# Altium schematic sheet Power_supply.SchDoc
size A3; SheetNumber: 1; SheetTotal: 1
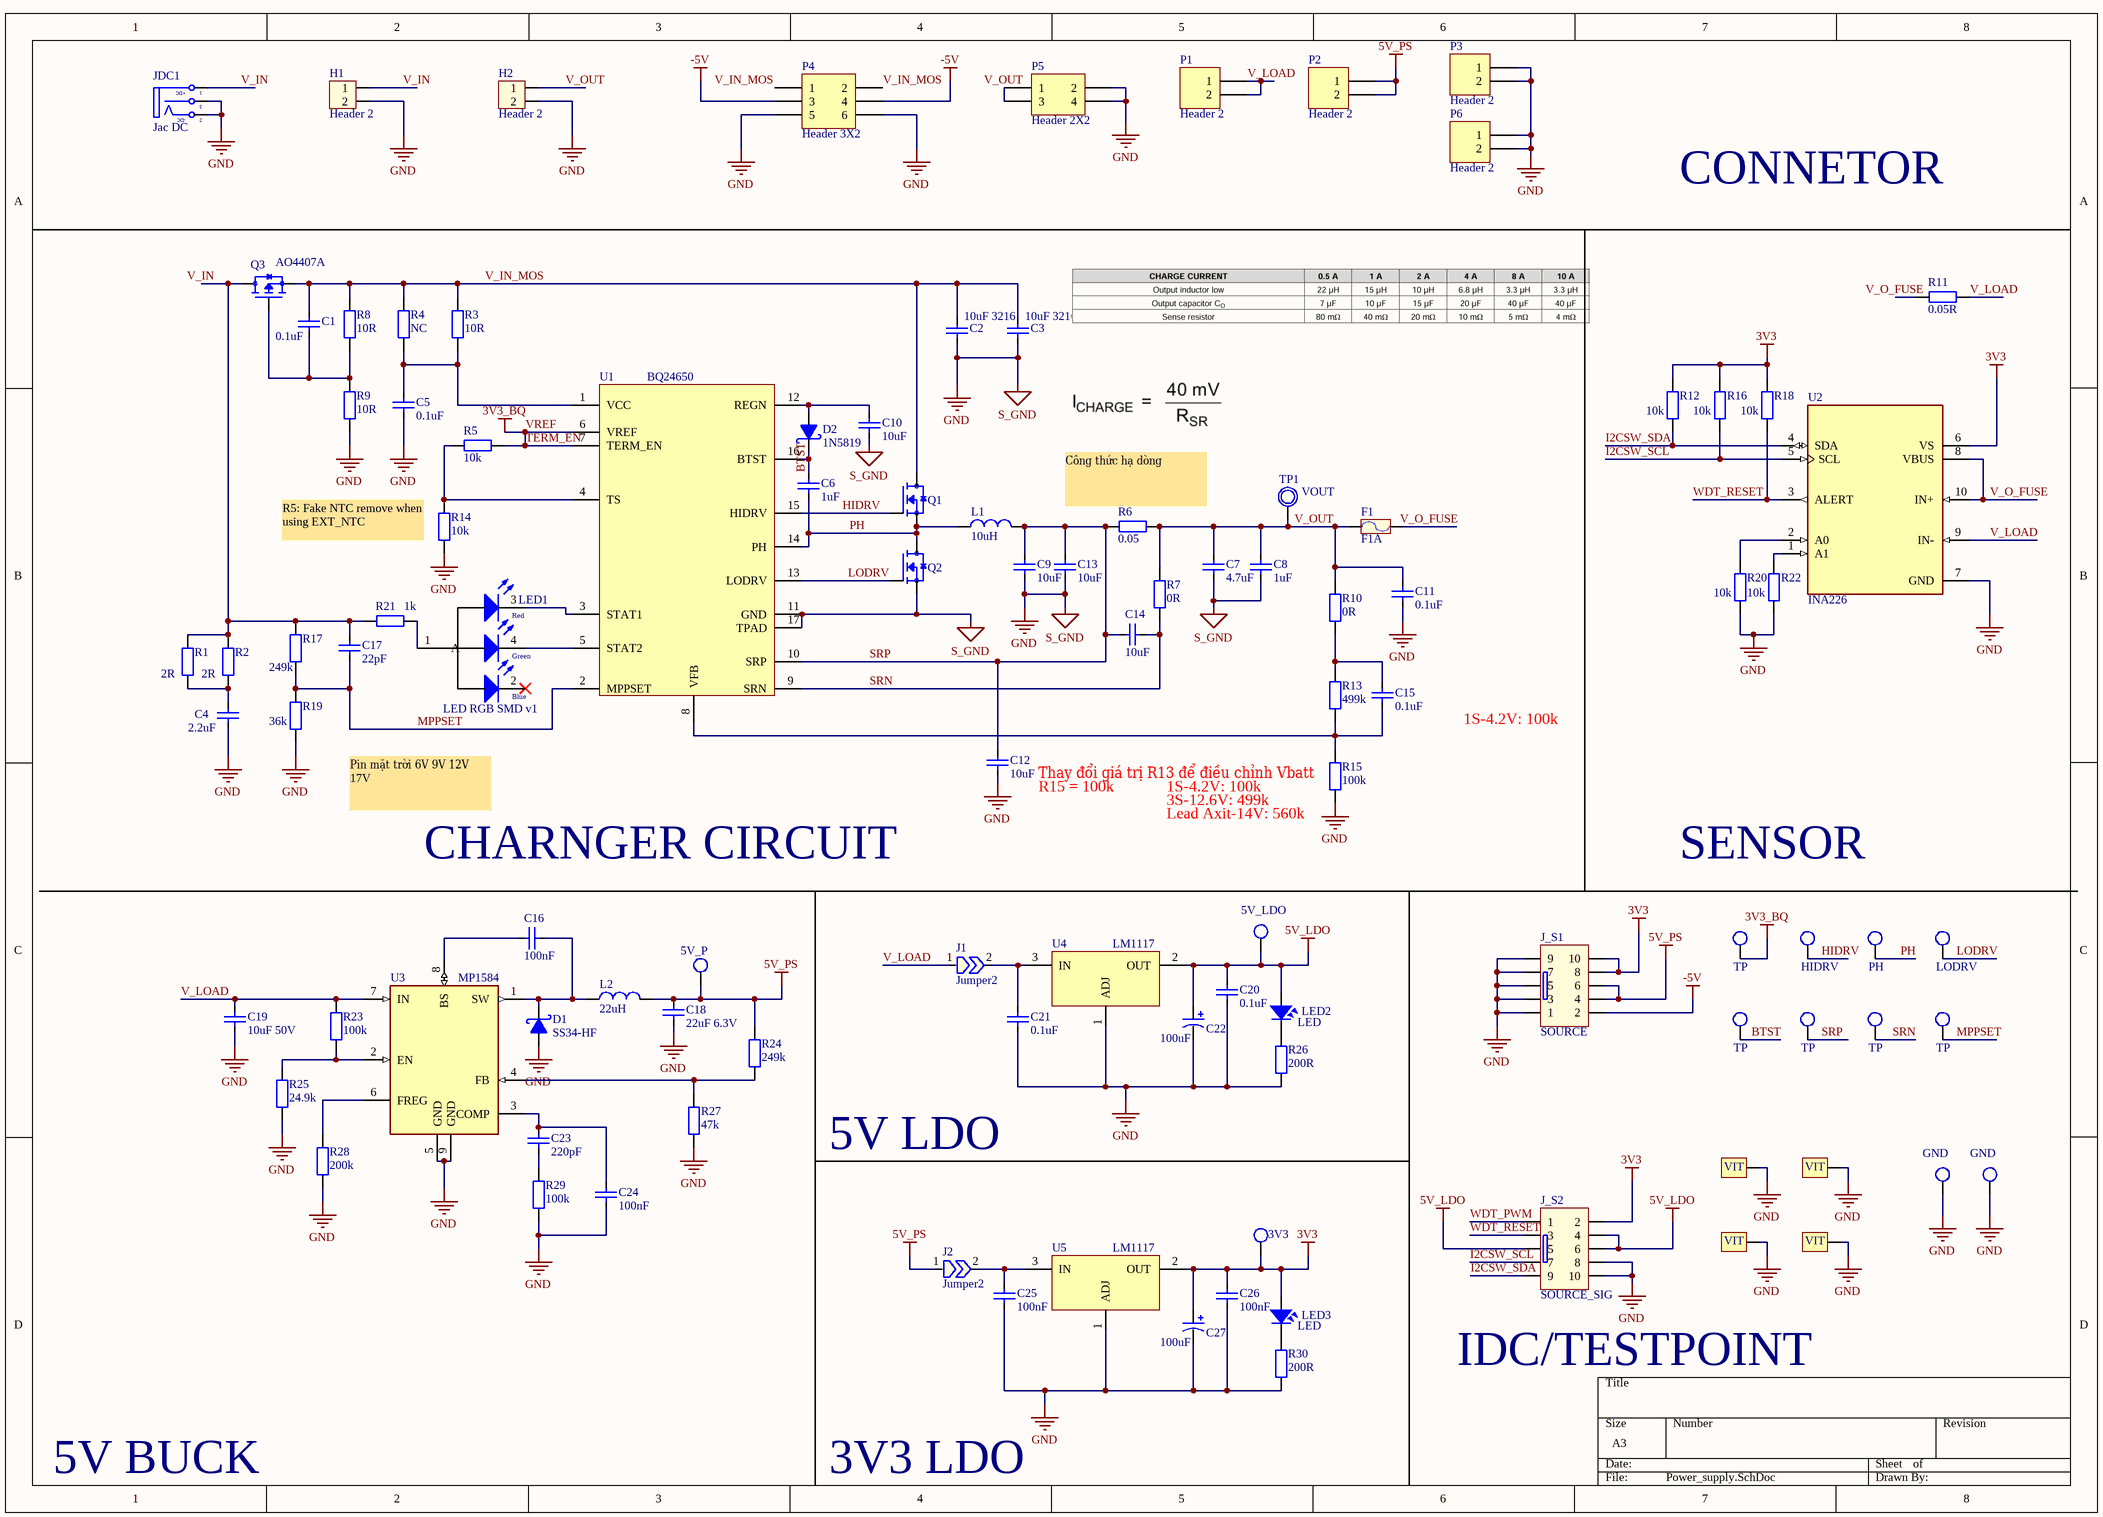
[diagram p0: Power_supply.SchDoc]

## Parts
C1  0.1uF  [CAP_0805]
C2  10uF 3216  [CAP_3216]
C3  10uF 3216  [CAP_3216]
C4  2.2uF  [CAP_0805]
C5  0.1uF  [CAP_0805]
C6  1uF  [CAP_0805]
C7  4.7uF  [CAP_1206]
C8  1uF  [CAP_1206]
C9  10uF  [CAP_1206]
C10  10uF  [CAP_0805]
C11  0.1uF  [CAP_0805]
C12  10uF  [CAP_0805]
C13  10uF  [CAP_1206]
C14  10uF  [CAP_0805]
C15  0.1uF  [CAP_0805]
C16  100nF  [CAP_0805]
C17  22pF  [CAP_0805]
C18  22uF 6.3V  [CAP_0805]
C19  10uF 50V  [CAP_3216]
C20  0.1uF  [CAP_0805]
C21  0.1uF  [CAP_0805]
C22  100uF  [CAP_7343]
C23  220pF  [CAP_0805]
C24  100nF  [CAP_0805]
C25  100nF  [CAP_0805]
C26  100nF  [CAP_0805]
C27  100uF  [CAP_7343]
D1  SS34-HF  [SMA]
D2  1N5819  [SMA]
F1  F1A  [RES-SMD-1812]
H1  Header 2  [HED2]
H2  Header 2  [HED2]
J1  Jumper2  [JUMPER2]  (no BOM)
J2  Jumper2  [JUMPER2]  (no BOM)
J_S1  SOURCE  [IDC10]
J_S2  SOURCE_SIG  [IDC10]
JDC1  Jac DC  [DC-IN]
L1  10uH  [L-SMD-M-12x10]
L2  22uH  [L-SMD-M-7.3x4.5]
LED1  LED RGB SMD v1  [LED RGB 3528]
LED2  LED  [LED-0805-Blue]
LED3  LED  [LED-0805-Blue]
P1  Header 2  [HDR1X2]
P2  Header 2  [HDR1X2]
P3  Header 2  [HDR1X2]
P4  Header 3X2  [HDR2X3]
P5  Header 2X2  [HDR2X2]
P6  Header 2  [HDR1X2]
P7  5V_P  [Testpoint 50ml]  (no BOM)
P8  5V_LDO  [Testpoint 50ml]  (no BOM)
P9  GND  [Testpoint 50ml]  (no BOM)
P10  GND  [Testpoint 50ml]  (no BOM)
P11  3V3  [Testpoint 50ml]  (no BOM)
Q1  AON6508  [MOSFET_HP_8Pin]  (value not drawn)
Q2  AON6508  [MOSFET_HP_8Pin]  (value not drawn)
Q3  AO4407A  [SOIC-8]
R1  2R  [RES-SMD-2512]
R2  2R  [RES-SMD-2512]
R3  10R  [RES-SMD-0805]
R4  NC  [RES-SMD-0805]
R5  10k  [RES-SMD-0805]
R6  0.05  [RES-SMD-2512]
R7  0R  [RES-SMD-0805]
R8  10R  [RES-SMD-0805]
R9  10R  [RES-SMD-0805]
R10  0R  [RES-SMD-0805]
R11  0.05R  [RES-SMD-2512]
R12  10k  [RES-SMD-0805]
R13  499k  [RES-SMD-0805]
R14  10k  [RES-SMD-0805]
R15  100k  [RES-SMD-0805]
R16  10k  [RES-SMD-0805]
R17  249k  [RES-SMD-0805]
R18  10k  [RES-SMD-0805]
R19  36k  [RES-SMD-0805]
R20  10k  [RES-SMD-0805]
R21  1k  [RES-SMD-0805]
R22  10k  [RES-SMD-0805]
R23  100k  [RES-SMD-0805]
R24  249k  [RES-SMD-0805]
R25  24.9k  [RES-SMD-0805]
R26  200R  [RES-SMD-0805]
R27  47k  [RES-SMD-0805]
R28  200k  [RES-SMD-0805]
R29  100k  [RES-SMD-0805]
R30  200R  [RES-SMD-0805]
TP1  VOUT  [TP1]
TP2  TP  [Testpoint 50ml]
TP3  HIDRV  [Testpoint 50ml]
TP4  PH  [Testpoint 50ml]
TP5  LODRV  [Testpoint 50ml]
TP6  TP  [Testpoint 50ml]
TP7  TP  [Testpoint 50ml]
TP8  TP  [Testpoint 50ml]
TP9  TP  [Testpoint 50ml]
U1  BQ24650  [VQFN-16]
U2  INA226  [VSSOP-10]
U3  MP1584  [SOP8-PP]
U4  LM1117  [SOT-223]
U5  LM1117  [SOT-223]
VIT1  1  [Screw Hole 4mm]  (value not drawn)  (net tie, no BOM)
VIT2  1  [Screw Hole 4mm]  (value not drawn)  (net tie, no BOM)
VIT3  1  [Screw Hole 4mm]  (value not drawn)  (net tie, no BOM)
VIT4  1  [Screw Hole 4mm]  (value not drawn)  (net tie, no BOM)

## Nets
3V3: C26.2 C27.1 J_S1.8 J_S1.10 J_S2.2 LED3.1 P11.1 R12.1 R16.1 R18.1 U2.6(VS) U5.2(OUT)
5V_LDO: C20.2 C22.1 J_S2.4 J_S2.5 J_S2.6 LED2.1 P8.1 U4.2(OUT)
5V_PS: C18.2 J2.1 J_S1.4 J_S1.6 L2.2 P2.1 P2.2 P7.1 R24.1
-5V: J_S1.2 P4.3 P4.4
GND: C2.1 C3.1 C4.1 C5.1 C7.2 C8.2 C9.1 C10.1 C11.1 C12.1 C13.1 C18.1 C19.1 C20.1 C21.1 C22.2 C24.1 C25.1 C26.1 C27.2 D1.1(A) H1.2 H2.2 J_S1.1 J_S1.3 J_S1.5 J_S1.7 J_S1.9 J_S2.8 J_S2.10 JDC1.2(TN) JDC1.3(S) P3.1 P3.2 P4.5 P4.6 P5.2 P5.4 P6.1 P6.2 P9.1 P10.1 Q2.1,2,3(S) R9.2 R14.2 R15.2 R19.2 R20.2 R22.2 R25.2 R26.2 R27.2 R28.2 R29.2 R30.2 U1.11(GND) U1.17(TPAD) U2.7(GND) U3.5(GND) U3.9(GND) U4.1(ADJ) U5.1(ADJ) VIT1.VIT1 VIT2.VIT1 VIT3.VIT1 VIT4.VIT1  [also labelled S_GND]
TERM_EN: R5.2 TP2.1 U1.6(VREF) U1.7(TERM_EN)  [also labelled 3V3_BQ, VREF]
BTST: C6.2 D2.2(K) TP6.1 U1.16(BTST)
HIDRV: Q1.4(G) TP3.1 U1.15(HIDRV)
I2CSW_SCL: J_S2.7 R16.2 U2.5(SCL)
I2CSW_SDA: J_S2.9 R12.2 U2.4(SDA)
LODRV: Q2.4(G) TP5.1 U1.13(LODRV)
MPPSET: C17.1 R17.2 R19.1 TP9.1 U1.2(MPPSET)
PH: C6.1 L1.1 Q1.1,2,3(S) Q2.5,6,7,8,9(D) TP4.1 U1.14(PH)
SRN: C14.1 R7.2 TP8.1 U1.9(SRN)
SRP: C9.2 C12.2 C13.2 C14.2 L1.2 R6.2 TP7.1 U1.10(SRP)
V_IN: C17.2 H1.1 JDC1.1(T) Q3.5,_6,_7,_8(D) R1.1 R2.1 R17.1 R21.2
V_IN_MOS: C1.2 C2.2 C3.2 P4.1 P4.2 Q1.5,6,7,8,9(D) Q3.1,_2,_3(S) R3.1 R4.1 R8.1
V_LOAD: C19.2 J1.1 P1.1 P1.2 R11.1 R23.1 U2.9(IN-) U3.7(IN)
V_O_FUSE: F1.2 R11.2 U2.8(VBUS) U2.10(IN+)
V_OUT: C7.1 C8.1 C11.2 F1.1 H2.1 P5.1 P5.3 R6.1 R7.1 R10.1 TP1.1
WDT_PWM: J_S2.1
WDT_RESET: J_S2.3 R18.2 U2.3(ALERT)
NetC1_1: C1.1 Q3.4(G) R8.2 R9.1
NetC4_2: C4.2 R1.2 R2.2
NetC5_2: C5.2 R3.2 R4.2 U1.1(VCC)
NetC10_2: C10.2 D2.1(A) U1.12(REGN)
NetC15_1: C15.1 R13.2 R15.1 U1.8(VFB)
NetC15_2: C15.2 R10.2 R13.1
NetC16_1: C16.1 U3.8(BS)
NetC16_2: C16.2 D1.2(K) L2.1 U3.1(SW)
NetC21_2: C21.2 J1.2 U4.3(IN)
NetC23_1: C23.1 R29.1
NetC23_2: C23.2 C24.2 U3.3(COMP)
NetC25_2: C25.2 J2.2 U5.3(IN)
NetLED1_1: LED1.1(A) R21.1
NetLED1_3: LED1.3(C2) U1.3(STAT1)
NetLED1_4: LED1.4(C1) U1.5(STAT2)
NetLED2_2: LED2.2 R26.1
NetLED3_2: LED3.2 R30.1
NetR5_1: R5.1 R14.1 U1.4(TS)
NetR20_1: R20.1 U2.2(A0)
NetR22_1: R22.1 U2.1(A1)
NetR23_2: R23.2 R25.1 U3.2(EN)
NetR24_2: R24.2 R27.1 U3.4(FB)
NetR28_1: R28.1 U3.6(FREG)

Not connected (* = marked no-connect by the designer): LED1 2(C3)*

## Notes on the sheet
- CONNETOR
- (near R6) Công thức hạ dòng
- (near R14) R5: Fake NTC remove when using EXT_NTC
- 1S-4.2V: 100k
- (near R15) Thay đổi giá trị R13 để điều chỉnh Vbatt
- (near C12) R15 = 100k
- Pin mặt trời 6V 9V 12V 17V
- CHARNGER CIRCUIT
- 3S-12.6V: 499k
- (near R15) Lead Axit-14V: 560k
- SENSOR
- 5V LDO
- (near J_S2) IDC/TESTPOINT
- 5V BUCK
- 3V3 LDO

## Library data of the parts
C1-C15 C17 = CapSMD: Capacitor; Value: 33p
C16 C18 C20 C21 C23-C26 = CapSMD: C 0805; Value: 33p
C19 = CapSMD: C 1206; Value: 33p
C22 C27 = CAP_TAN_SMD: C Tan 7343
D1 D2 = 1N5822: Schottky Rectifiers; Value: Diode c?m 1N5408
F1 = Fuse: Fuse 5A; Designed by: VanDungEvn
H1 H2 = Hed2: Header 2 (Green)
J1 J2 = Jumper2: Jumper, 2-Pin
J_S1 J_S2 = IDC 5X2: Value: Header 5x2
JDC1 = DCIN: Jac DC input
L1 = Inductor: Value: 150 mH
L2 = Inductor: 6.8-10uH; Value: 150 mH
LED2 LED3 = LED: LED Single colour Green and Red; Value: LED 3 ly Single Colour
P1-P3 P6 = Header 2: Header, 2-Pin
P4 = Header 3X2: Header, 3-Pin, Dual row
P5 = Header 2X2: Header, 2-Pin, Dual row
P7-P11 TP2-TP9 = TP_1: Test Point
Q1 Q2 = MOSFET-N: MFET-CHP
Q3 = MOSFET-P: MFET-ChP
R1 R2 R6 = Resistor - SMD: Resistor - SMD 2512; Manufacturer: Generic Components; Class: Passive
R3-R5 R7 R10 R13-R15 R17 R19 R21 = Resistor - SMD: Resistor - SMD 0805; Manufacturer: Generic Components; Class: Passive
R8 R9 R12 R16 R18 R20 R22 R23 R26 R28-R30 = Resistor - SMD: R 0805; Manufacturer: Generic Components; Class: Passive
R11 = Resistor - SMD: R 2512 1%; Manufacturer: Generic Components; Class: Passive
R24 R25 R27 = Resistor - SMD: R 0805 1%; Manufacturer: Generic Components; Class: Passive
TP1 = TP1: Test Point
U1 = BQ24650: BQ24650 Stand-Alone Synchronous Buck Battery Charge Controller for Solar Power / With Maximum Power Point Tracking
U2 = INA226: Current Sensing IC
U3 = MP1584: MP1584, The wide 4.5V to 28V input range accommodates a   variety   of   step-down   applications, SOIC8E
U4 U5 = LM1117: 3V3 5V LDO, AMS1117, LDI1117
VIT1-VIT4 = VIT: Oc Vit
